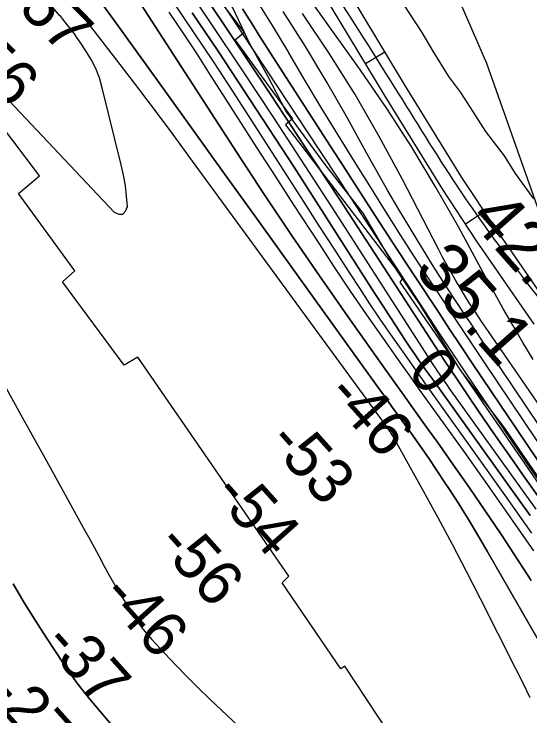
# Model space of a CAD drawing. Extents: x 3245246 to 3283090, y 806824 to 832173.
# Drawn here: x 3270426 to 3271110, y 818378 to 819309 of the extents above; entities that cross this region are included whole.
import ezdxf

# ---------------------------------------------------------------- set-up
doc = ezdxf.new("R2010")
doc.units = 0
for name, color, linetype in [('V-RIVR-EDGE', 7, 'Continuous'), ('V-RIVR-RANG', 7, 'Continuous'), ('V-ROAD-CNTR', 7, 'Continuous'), ('V-RRAP-RVMT', 7, 'Continuous'), ('V-SITE-VEGE', 7, 'Continuous'), ('V-TOPO-DPTH', 7, 'Continuous'), ('V-TOPO-MAJR', 7, 'Continuous'), ('V-TOPO-MINR', 7, 'Continuous'), ('V-TOPO-WATR', 7, 'Continuous'), ('V-WETL-SWMP', 7, 'Continuous')]:
    doc.layers.add(name, color=color, linetype=linetype)

msp = doc.modelspace()

# ---------------------------------------------------------------- linework, layer by layer
at = {"layer": 'V-RIVR-EDGE'}
msp.add_lwpolyline([(3271126.46, 818687.14), (3271077.08, 818759.41), (3271017.29, 818837.8), (3270964.91, 818923.13), (3270933.72, 818969.28), (3270889.14, 819044.59), (3270838.88, 819109.05), (3270786.89, 819180.47), (3270762.66, 819226.17), (3270738.43, 819270.13), (3270716.38, 819317.13), (3270684.76, 819361.98), (3270641.86, 819418.6), (3270597.25, 819482.17), (3270572.13, 819521.35), (3270540.92, 819554.9), (3270518.83, 819587.99)], dxfattribs=at)
at = {"layer": 'V-ROAD-CNTR'}
for p, q in [((3270917.85, 819258.03), (3270892.16, 819242.53)), ((3271049.85, 819046.46), (3271024.81, 819029.94))]:
    msp.add_line(p, q, dxfattribs=at)
for points in [[(3269843.4, 820720.01), (3269850.17, 820706.17), (3269882.17, 820651.66), (3269977.9, 820546.49), (3270017.59, 820500.24), (3270105.1, 820401.13), (3270161.44, 820338.84), (3270271.07, 820208.57), (3270367.8, 820073.22), (3270400.77, 820019.63), (3270480.26, 819915.46), (3270531.02, 819842.71), (3270596.3, 819744.33), (3270689.08, 819609.75), (3270760.57, 819510.58), (3270844.44, 819379.61), (3270883.47, 819315.02), (3270943.57, 819215.39), (3271019.73, 819092.11), (3271064.12, 819024.84), (3271139.99, 818915.3)], [(3269823.72, 820691.96), (3269857.88, 820633.78), (3269955.42, 820526.62), (3269994.96, 820480.54), (3270082.73, 820381.14), (3270138.83, 820319.11), (3270247.35, 820190.16), (3270342.79, 820056.62), (3270376.01, 820002.63), (3270456.03, 819897.77), (3270506.22, 819825.84), (3270571.45, 819727.53), (3270664.56, 819592.46), (3270735.75, 819493.7), (3270818.96, 819363.76), (3270857.79, 819299.51), (3270917.97, 819199.76), (3270994.44, 819075.96), (3271039.26, 819008.03), (3271115.77, 818897.58)]]:
    msp.add_lwpolyline(points, dxfattribs=at)
for points in [[(3268554.95, 824466.19), (3268928.09, 824288.38), (3269383.1, 824061.94), (3269668.74, 823890.07), (3270076.6, 823640.14), (3270419.33, 823451), (3270842.02, 823197.94), (3271162.23, 823029.36), (3271548.34, 822792.54), (3271898.38, 822578.38), (3272236.86, 822400.28), (3272509.78, 822239.3), (3272743.9, 822091.31), (3273013.63, 821941.14), (3273341.05, 821721.19), (3273731.8, 821490.06), (3274189.22, 821174.99), (3274593.6, 820901.16), (3274916.65, 820684.25), (3275373.15, 820360.04), (3275676.64, 820160.98), (3275802.37, 820045.11), (3275896.21, 819927.97), (3275965.24, 819818.62), (3276015.07, 819699.55), (3276044.42, 819586.74), (3276100.52, 819412.97), (3276190.86, 819208.33), (3276292.53, 819051.84), (3276415.54, 818926.3), (3276568.23, 818833.94), (3276716.18, 818768.83), (3276924.78, 818729.04), (3277119.88, 818725), (3277260.84, 818758.15)], [(3265843.13, 823432.94), (3265858.98, 823417.12), (3265884.36, 823393.48), (3265921.56, 823385.9), (3265988.57, 823351.07), (3266047.21, 823332.33), (3266110.89, 823317.69), (3266174.63, 823302.49), (3266237.94, 823256.14), (3266318.96, 823213.69), (3266446.25, 823144.04), (3266598.22, 823070.18), (3266698.27, 823024.21), (3266809.76, 822977.55), (3266902.83, 822954.65), (3266981.51, 822929.37), (3267047.02, 822922.93), (3267126.67, 822926.97), (3267196.8, 822934.46), (3267240.76, 822931.16), (3267315.46, 822929.02), (3267389.48, 822902.91), (3267472.52, 822855.33), (3267548.21, 822799.11), (3267673.18, 822703.23), (3267729.53, 822659.19), (3267800.82, 822580.02), (3267841.58, 822514.78), (3267890.36, 822443.64), (3267961.46, 822390.31), (3268026.22, 822347.95), (3268097.47, 822313.66), (3268226.82, 822221.48), (3268328.91, 822136.16), (3268437.97, 822030.19), (3268539.63, 821913.73), (3268611.4, 821855.02), (3268669.68, 821832.99), (3268741.62, 821835.21), (3268780.98, 821862.31), (3268824.18, 821916.6), (3268873.06, 822006.27), (3268932.52, 822098.07), (3268972.12, 822145.49), (3269019.4, 822162.03), (3269055.98, 822158.33), (3269086.75, 822138.72), (3269215.73, 821995.56), (3269467.12, 821682.49), (3269665.02, 821425.34), (3269890.24, 821132.34), (3269935.57, 821060.84), (3269937.76, 820947.01), (3269911.92, 820878.37), (3269882.42, 820803.43), (3269850.37, 820754.68), (3269820.83, 820702.94), (3269847.45, 820661.45), (3269995.31, 820504.9), (3270135.08, 820342.32), (3270215.8, 820249.25), (3270280.88, 820161.54), (3270409.84, 819983.24), (3270585.16, 819734.7), (3270723.07, 819531.19), (3270847.77, 819342.24), (3270941.21, 819194.89), (3271024.16, 819065.03), (3271103.72, 818955.95), (3271217.86, 818809.2), (3271322.11, 818665.04), (3271450.94, 818481.15), (3271547.8, 818329.85), (3271656.16, 818158.96), (3271778.9, 817965.4), (3271939.04, 817707.54), (3272036.56, 817466.51), (3272126.72, 817285.29), (3272211.94, 817051.13), (3272318, 816867.47), (3272429.35, 816683.19), (3272508.65, 816556.22), (3272571.56, 816398.68), (3272670.41, 816197), (3272779.92, 816022.86), (3272872.13, 815803.22), (3272964.65, 815556.57)]]:
    msp.add_spline(points, degree=3, dxfattribs=at)
at = {"layer": 'V-RRAP-RVMT'}
for p, q in [((3270576.47, 819485.37), (3270731.47, 819284.38)), ((3270576.47, 819485.37), (3270731.47, 819284.38)), ((3270459.93, 819093.98), (3270248.21, 819374.66)), ((3270459.93, 819093.98), (3270248.21, 819374.66)), ((3270731.47, 819284.38), (3270719.54, 819273.97)), ((3270731.47, 819284.38), (3270719.54, 819273.97)), ((3270719.54, 819273.97), (3270795.32, 819169.81)), ((3270719.54, 819273.97), (3270795.32, 819169.81)), ((3270795.32, 819169.81), (3270786.18, 819161.78)), ((3270795.32, 819169.81), (3270786.18, 819161.78)), ((3270786.18, 819161.78), (3270942.07, 818958.53)), ((3270786.18, 819161.78), (3270942.07, 818958.53)), ((3270432.17, 819070.79), (3270459.93, 819093.98)), ((3270432.17, 819070.79), (3270459.93, 819093.98)), ((3270506.73, 818968.19), (3270432.17, 819070.79)), ((3270506.73, 818968.19), (3270432.17, 819070.79)), ((3270490.26, 818953.79), (3270506.73, 818968.19)), ((3270490.26, 818953.79), (3270506.73, 818968.19)), ((3270572.42, 818843.06), (3270490.26, 818953.79)), ((3270572.42, 818843.06), (3270490.26, 818953.79)), ((3270942.07, 818958.53), (3270937.79, 818952.98)), ((3270942.07, 818958.53), (3270937.79, 818952.98)), ((3270937.79, 818952.98), (3271222.9, 818538.45)), ((3270937.79, 818952.98), (3271222.9, 818538.45)), ((3270590.46, 818853.51), (3270572.42, 818843.06)), ((3270590.46, 818853.51), (3270572.42, 818843.06)), ((3270790.66, 818563.47), (3270590.46, 818853.51)), ((3270790.66, 818563.47), (3270590.46, 818853.51)), ((3270781.69, 818554.58), (3270790.66, 818563.47)), ((3270781.69, 818554.58), (3270790.66, 818563.47)), ((3270859.83, 818440.41), (3270781.69, 818554.58)), ((3270859.83, 818440.41), (3270781.69, 818554.58)), ((3270864.98, 818443.82), (3270859.83, 818440.41)), ((3270864.98, 818443.82), (3270859.83, 818440.41)), ((3270934.23, 818339.06), (3270864.98, 818443.82)), ((3270934.23, 818339.06), (3270864.98, 818443.82))]:
    msp.add_line(p, q, dxfattribs=at)
at = {"layer": 'V-SITE-VEGE'}
for p, q in [((3270967.57, 819284.18), (3270943.09, 819321.33)), ((3270982.24, 819259.42), (3270967.57, 819284.18)), ((3271003.04, 819225.99), (3270982.24, 819259.42)), ((3271018.97, 819204.92), (3271003.04, 819225.99)), ((3271038.55, 819173.96), (3271018.97, 819204.92)), ((3271052.01, 819152.92), (3271038.55, 819173.96)), ((3271076.52, 819120.7), (3271052.01, 819152.92)), ((3271091.2, 819097.17), (3271076.52, 819120.7)), ((3271115.7, 819063.72), (3271091.2, 819097.17))]:
    msp.add_line(p, q, dxfattribs=at)
at = {"layer": 'V-TOPO-DPTH'}
for points in [[(3270633.36, 819401.85), (3270719.25, 819273.05), (3270765.92, 819202.77), (3270812.4, 819132.38), (3270858.61, 819061.8), (3270904.64, 818991.1), (3270962.02, 818902.59), (3270979.31, 818876.12), (3270996.72, 818849.73), (3271014.31, 818823.45), (3271032.02, 818797.26), (3271049.89, 818771.17), (3271067.86, 818745.16), (3271085.98, 818719.25), (3271104.2, 818693.41), (3271158.62, 818616.7)], [(3271158.62, 818616.7), (3271104.2, 818693.41), (3271085.98, 818719.25), (3271067.86, 818745.16), (3271049.89, 818771.17), (3271032.02, 818797.26), (3271014.31, 818823.45), (3270996.72, 818849.73), (3270979.31, 818876.12), (3270962.02, 818902.59), (3270904.64, 818991.1), (3270858.61, 819061.8), (3270812.4, 819132.38), (3270765.92, 819202.77), (3270719.25, 819273.05), (3270633.36, 819401.85)], [(3271175.17, 818385.21), (3271053.66, 818596.5), (3271041.34, 818617.51), (3271028.8, 818638.38), (3271015.91, 818659.04), (3271002.79, 818679.56), (3270998.17, 818686.65), (3270987.07, 818703.44), (3270975.82, 818720.12), (3270964.33, 818736.64), (3270952.69, 818753.06), (3270940.93, 818769.4), (3270929.18, 818785.73), (3270917.43, 818802.07), (3270905.68, 818818.41), (3270796.17, 818970.71), (3270751.27, 819033.16), (3270706.37, 819095.6), (3270661.47, 819158.04), (3270616.57, 819220.49), (3270561.73, 819296.76), (3270544.19, 819321.02)], [(3270544.19, 819321.02), (3270561.73, 819296.76), (3270616.57, 819220.49), (3270661.47, 819158.04), (3270706.37, 819095.6), (3270751.27, 819033.16), (3270796.17, 818970.71), (3270905.68, 818818.41), (3270917.43, 818802.07), (3270929.18, 818785.73), (3270940.93, 818769.4), (3270952.69, 818753.06), (3270964.33, 818736.64), (3270975.82, 818720.12), (3270987.07, 818703.44), (3270998.17, 818686.65), (3271002.79, 818679.56), (3271015.91, 818659.04), (3271028.8, 818638.38), (3271041.34, 818617.51), (3271053.66, 818596.5), (3271175.17, 818385.21)], [(3270594.48, 819322.02), (3270721.59, 819125.12), (3270757.55, 819070.22), (3270793.98, 819015.64), (3270831.13, 818961.54), (3270868.75, 818907.77), (3270914.18, 818843.75), (3270929.47, 818822.24), (3270944.78, 818800.76), (3270960.13, 818779.29), (3270975.5, 818757.85), (3270987.78, 818740.76), (3271009.14, 818710.67), (3271030.27, 818680.42), (3271051.07, 818649.94), (3271071.65, 818619.31), (3271089.96, 818591.7), (3271112.23, 818557.58)], [(3270594.48, 819322.02), (3270721.59, 819125.12), (3270757.55, 819070.22), (3270793.98, 819015.64), (3270831.13, 818961.54), (3270868.75, 818907.77), (3270914.18, 818843.75), (3270929.47, 818822.24), (3270944.78, 818800.76), (3270960.13, 818779.29), (3270975.5, 818757.85), (3270987.78, 818740.76), (3271009.14, 818710.67), (3271030.27, 818680.42), (3271051.07, 818649.94), (3271071.65, 818619.31), (3271089.96, 818591.7), (3271112.23, 818557.58)], [(3270729.14, 819315.53), (3270741.4, 819296.22), (3270753.71, 819276.95), (3270836.56, 819147.81), (3270866.58, 819101.17), (3270896.71, 819054.59), (3270926.97, 819008.1), (3270957.33, 818961.67), (3270989.4, 818912.8), (3271003.85, 818890.89), (3271018.34, 818869.01), (3271032.93, 818847.19), (3271047.57, 818825.41), (3271165.94, 818650.01)], [(3271115.76, 818596.67), (3271085.11, 818640.79), (3271054.15, 818684.7), (3271023, 818728.48), (3270978.46, 818790.63), (3270969.44, 818803.23), (3270960.44, 818815.85), (3270951.46, 818828.48), (3270942.5, 818841.13), (3270916.16, 818878.35), (3270894.23, 818909.74), (3270872.56, 818941.31), (3270851.27, 818973.13), (3270830.23, 819005.12), (3270797.37, 819055.76), (3270772.82, 819093.69), (3270748.33, 819131.67), (3270723.95, 819169.72), (3270699.63, 819207.81), (3270686.95, 819227.73), (3270668.87, 819255.78), (3270650.57, 819283.69), (3270631.95, 819311.39)], [(3271115.76, 818596.67), (3271085.11, 818640.79), (3271054.15, 818684.7), (3271023, 818728.48), (3270978.46, 818790.63), (3270969.44, 818803.23), (3270960.44, 818815.85), (3270951.46, 818828.48), (3270942.5, 818841.13), (3270916.16, 818878.35), (3270894.23, 818909.74), (3270872.56, 818941.31), (3270851.27, 818973.13), (3270830.23, 819005.12), (3270797.37, 819055.76), (3270772.82, 819093.69), (3270748.33, 819131.67), (3270723.95, 819169.72), (3270699.63, 819207.81), (3270686.95, 819227.73), (3270668.87, 819255.78), (3270650.57, 819283.69), (3270631.95, 819311.39)], [(3270662.56, 819310.28), (3270696.79, 819259.44), (3270730.74, 819208.42), (3270764.27, 819157.12), (3270797.53, 819105.65), (3270896.72, 818950.73), (3270905.71, 818936.73), (3270914.73, 818922.73), (3270923.79, 818908.76), (3270932.87, 818894.81), (3270939.1, 818885.26), (3270945.13, 818876.12), (3270951.22, 818867.03), (3270957.41, 818858.01), (3270963.67, 818849.03), (3270971.14, 818838.43), (3270973.72, 818834.79), (3270976.3, 818831.14), (3270978.9, 818827.51), (3270981.5, 818823.87), (3271079.5, 818687.39), (3271110.65, 818643.68)], [(3271110.65, 818643.68), (3271079.5, 818687.39), (3270981.5, 818823.87), (3270978.9, 818827.51), (3270976.3, 818831.14), (3270973.72, 818834.79), (3270971.14, 818838.43), (3270963.67, 818849.03), (3270957.41, 818858.01), (3270951.22, 818867.03), (3270945.13, 818876.12), (3270939.1, 818885.26), (3270932.87, 818894.81), (3270923.79, 818908.76), (3270914.73, 818922.73), (3270905.71, 818936.73), (3270896.72, 818950.73), (3270797.53, 819105.65), (3270764.27, 819157.12), (3270730.74, 819208.42), (3270696.79, 819259.44), (3270662.56, 819310.28)], [(3270425.24, 818553.18), (3270439.33, 818528.91), (3270454.05, 818505.04), (3270469.21, 818481.42), (3270492.26, 818446.51), (3270500.91, 818433.92), (3270509.84, 818421.54), (3270519.21, 818409.49), (3270528.87, 818397.65), (3270569.75, 818349.32)], [(3270569.75, 818349.32), (3270528.87, 818397.65), (3270519.21, 818409.49), (3270509.84, 818421.54), (3270500.91, 818433.92), (3270492.26, 818446.51), (3270469.21, 818481.42), (3270454.05, 818505.04), (3270439.33, 818528.91), (3270425.24, 818553.18)]]:
    msp.add_lwpolyline(points, dxfattribs=at)
at = {"layer": 'V-TOPO-MAJR'}
for points in [[(3271110.77, 818401.83), (3271101.4, 818421.16), (3271091.84, 818440.4), (3271044.78, 818533.39), (3271026.36, 818569.3), (3271007.67, 818605.07), (3270988.59, 818640.63), (3270969.24, 818676.05), (3270933.96, 818739.77), (3270932.02, 818743.2), (3270930.02, 818746.61), (3270927.96, 818749.98), (3270925.86, 818753.32), (3270925.21, 818754.33), (3270923.37, 818757.13), (3270921.5, 818759.92), (3270919.59, 818762.67), (3270917.65, 818765.41), (3270916.23, 818767.38), (3270914.98, 818769.11), (3270913.72, 818770.84), (3270912.47, 818772.57), (3270911.21, 818774.3), (3270663.05, 819113.75), (3270637.13, 819148.9), (3270611.02, 819183.91), (3270584.64, 819218.71), (3270558.06, 819253.37), (3270521.78, 819300.31), (3270513.16, 819311.36)], [(3271124.93, 818787.09), (3271099.64, 818823.53), (3271055.46, 818887.61), (3271052.38, 818892.1), (3271049.32, 818896.61), (3271046.28, 818901.13), (3271043.27, 818905.66), (3271036.4, 818916.05), (3271030.04, 818925.84), (3271023.79, 818935.7), (3271017.71, 818945.66), (3271011.73, 818955.68), (3271011.69, 818955.74), (3271005.86, 818965.89), (3271000.14, 818976.11), (3270994.58, 818986.41), (3270989.14, 818996.78), (3270941.11, 819090.08), (3270910.63, 819146.47), (3270878.66, 819201.96), (3270844.47, 819256.12), (3270808.79, 819309.38)], [(3270405.67, 818830.22), (3270437.47, 818773.19), (3270469.18, 818716.11), (3270518.53, 818627.07), (3270525.47, 818614.46), (3270532.36, 818601.82), (3270539.17, 818589.14), (3270545.94, 818576.44), (3270552.82, 818563.8), (3270559.9, 818551.27), (3270567.27, 818538.92), (3270574.84, 818526.69), (3270587.26, 818507.14), (3270592.23, 818499.77), (3270597.46, 818492.6), (3270603.07, 818485.73), (3270608.93, 818479.05), (3270625.99, 818460.66), (3270640.73, 818445.09), (3270655.68, 818429.72), (3270670.92, 818414.65), (3270686.37, 818399.79), (3270797.17, 818295.29)]]:
    msp.add_lwpolyline(points, dxfattribs=at)
at = {"layer": 'V-TOPO-MINR'}
for points in [[(3271114.57, 818850.43), (3271100.88, 818873.05), (3271087.61, 818895.93), (3271074.49, 818918.9), (3271061.6, 818942), (3271048.86, 818965.18), (3271015.57, 819026.48), (3270985.34, 819079.78), (3270953.84, 819132.29), (3270920.43, 819183.6), (3270885.74, 819234.11), (3270700.27, 819493.85), (3270695.78, 819500.11), (3270691.27, 819506.35), (3270686.72, 819512.58), (3270682.16, 819518.79), (3270677.67, 819525.05), (3270673.3, 819531.38), (3270669.11, 819537.84), (3270665.04, 819544.38), (3270664.9, 819544.6), (3270661.77, 819551.46), (3270659.73, 819558.5), (3270234.1, 820399.59)], [(3270412.74, 819201.36), (3270558.9, 819045.85), (3270565.19, 819043.41), (3270570.42, 819043.44), (3270574.06, 819047.2), (3270576.64, 819053.44), (3270575.5, 819067.41), (3270573.83, 819081.31), (3270571.39, 819095.09), (3270568.43, 819108.79), (3270543.28, 819211.11), (3270539.37, 819223.99), (3270534.6, 819236.49), (3270528.54, 819248.42), (3270521.61, 819259.97), (3270514.63, 819270.3), (3270510.45, 819276.33), (3270506.18, 819282.29), (3270501.77, 819288.14), (3270497.25, 819293.92), (3270490.73, 819302.08), (3270489.4, 819303.72), (3270488.06, 819305.36), (3270486.71, 819306.98), (3270485.34, 819308.59), (3270118.98, 819735.96)], [(3271133.69, 818673.65), (3271110.06, 818708.06), (3271086.55, 818742.57), (3271044.96, 818803.97), (3271026.28, 818831.7), (3271007.69, 818859.5), (3270989.24, 818887.39), (3270970.88, 818915.35), (3270930.86, 818976.64), (3270892.51, 819035.25), (3270854.1, 819093.82), (3270815.6, 819152.33), (3270777.03, 819210.79), (3270627.79, 819436.61)], [(3271118.56, 818652.33), (3271003.89, 818812.33), (3271000.7, 818816.81), (3270997.53, 818821.3), (3270994.39, 818825.81), (3270991.27, 818830.33), (3270988.18, 818834.88), (3270985.12, 818839.45), (3270982.1, 818844.04), (3270979.1, 818848.65), (3270853.22, 819044.43), (3270812.29, 819107.66), (3270771.09, 819170.72), (3270729.51, 819233.52), (3270687.66, 819296.15), (3270640.19, 819366.73)], [(3271113.14, 818620.33), (3271077.21, 818671.29), (3271041.04, 818722.08), (3270979.98, 818807.19), (3270974.15, 818815.32), (3270968.34, 818823.47), (3270962.55, 818831.62), (3270956.77, 818839.79), (3270939.9, 818863.67), (3270925.81, 818883.86), (3270911.88, 818904.16), (3270898.18, 818924.61), (3270884.63, 818945.17), (3270871.14, 818965.91), (3270851, 818996.95), (3270830.91, 819028.02), (3270810.91, 819059.14), (3270790.96, 819090.3), (3270742.19, 819166.69), (3270716.53, 819206.45), (3270690.62, 819246.03), (3270664.31, 819285.36), (3270637.74, 819324.52)], [(3271242.67, 818560.48), (3271050.17, 818846.45), (3271039.48, 818862.39), (3271028.82, 818878.35), (3271018.2, 818894.34), (3271007.62, 818910.35), (3270983.78, 818946.55), (3270961.43, 818980.76), (3270939.28, 819015.1), (3270917.4, 819049.61), (3270895.7, 819084.24), (3270877.77, 819113.11), (3270855.67, 819149), (3270833.74, 819185.01), (3270812.07, 819221.17), (3270790.59, 819257.44), (3270790.51, 819257.57), (3270768.86, 819293.65), (3270746.76, 819329.44)], [(3271175.17, 818385.21), (3271053.66, 818596.5), (3271041.34, 818617.51), (3271028.8, 818638.38), (3271015.91, 818659.04), (3271002.79, 818679.56), (3270998.17, 818686.65), (3270987.07, 818703.44), (3270975.82, 818720.12), (3270964.33, 818736.64), (3270952.69, 818753.06), (3270940.93, 818769.4), (3270929.18, 818785.73), (3270917.43, 818802.07), (3270905.68, 818818.41), (3270796.17, 818970.71), (3270751.27, 819033.16), (3270706.37, 819095.6), (3270661.47, 819158.04), (3270616.57, 819220.49), (3270561.73, 819296.76), (3270544.19, 819321.02)], [(3271112.23, 818557.58), (3271089.96, 818591.7), (3271071.65, 818619.31), (3271051.07, 818649.94), (3271030.27, 818680.42), (3271009.14, 818710.67), (3270987.78, 818740.76), (3270975.5, 818757.85), (3270960.13, 818779.29), (3270944.78, 818800.76), (3270929.47, 818822.24), (3270914.18, 818843.75), (3270868.75, 818907.77), (3270831.13, 818961.54), (3270793.98, 819015.64), (3270757.55, 819070.22), (3270721.59, 819125.12), (3270594.48, 819322.02)], [(3271165.94, 818650.01), (3271047.57, 818825.41), (3271032.93, 818847.19), (3271018.34, 818869.01), (3271003.85, 818890.89), (3270989.4, 818912.8), (3270957.33, 818961.67), (3270926.97, 819008.1), (3270896.71, 819054.59), (3270866.58, 819101.17), (3270836.56, 819147.81), (3270753.71, 819276.95), (3270741.4, 819296.22), (3270729.14, 819315.53)], [(3271115.76, 818596.67), (3271085.11, 818640.79), (3271054.15, 818684.7), (3271023, 818728.48), (3270978.46, 818790.63), (3270969.44, 818803.23), (3270960.44, 818815.85), (3270951.46, 818828.48), (3270942.5, 818841.13), (3270916.16, 818878.35), (3270894.23, 818909.74), (3270872.56, 818941.31), (3270851.27, 818973.13), (3270830.23, 819005.12), (3270797.37, 819055.76), (3270772.82, 819093.69), (3270748.33, 819131.67), (3270723.95, 819169.72), (3270699.63, 819207.81), (3270686.95, 819227.73), (3270668.87, 819255.78), (3270650.57, 819283.69), (3270631.95, 819311.39)], [(3271110.65, 818643.68), (3271079.5, 818687.39), (3270981.5, 818823.87), (3270978.9, 818827.51), (3270976.3, 818831.14), (3270973.72, 818834.79), (3270971.14, 818838.43), (3270963.67, 818849.03), (3270957.41, 818858.01), (3270951.22, 818867.03), (3270945.13, 818876.12), (3270939.1, 818885.26), (3270932.87, 818894.81), (3270923.79, 818908.76), (3270914.73, 818922.73), (3270905.71, 818936.73), (3270896.72, 818950.73), (3270797.53, 819105.65), (3270764.27, 819157.12), (3270730.74, 819208.42), (3270696.79, 819259.44), (3270662.56, 819310.28)], [(3271317.5, 818473.13), (3271052.77, 818867.17), (3271045.95, 818877.35), (3271039.14, 818887.55), (3271032.35, 818897.75), (3271025.58, 818907.97), (3271010.13, 818931.34), (3270995.79, 818953.34), (3270981.64, 818975.46), (3270967.76, 818997.75), (3270954.07, 819020.16), (3270951.4, 819024.59), (3270936.66, 819049.38), (3270922.11, 819074.29), (3270907.84, 819099.36), (3270893.77, 819124.54), (3270868.38, 819170.59), (3270841.05, 819218.45), (3270812.79, 819265.72), (3270783.13, 819312.13)], [(3270425.24, 818553.18), (3270439.33, 818528.91), (3270454.05, 818505.04), (3270469.21, 818481.42), (3270492.26, 818446.51), (3270500.91, 818433.92), (3270509.84, 818421.54), (3270519.21, 818409.49), (3270528.87, 818397.65), (3270569.75, 818349.32)]]:
    msp.add_lwpolyline(points, dxfattribs=at)
at = {"layer": 'V-TOPO-WATR'}
msp.add_lwpolyline([(3271158.62, 818616.7), (3271104.2, 818693.41), (3271085.98, 818719.25), (3271067.86, 818745.16), (3271049.89, 818771.17), (3271032.02, 818797.26), (3271014.31, 818823.45), (3270996.72, 818849.73), (3270979.31, 818876.12), (3270962.02, 818902.59), (3270904.64, 818991.1), (3270858.61, 819061.8), (3270812.4, 819132.38), (3270765.92, 819202.77), (3270719.25, 819273.05), (3270633.36, 819401.85)], dxfattribs=at)
at = {"layer": 'V-WETL-SWMP'}
msp.add_lwpolyline([(3271156.4, 818951.88), (3271053.1, 819243.25), (3270865.28, 819675.61), (3270743.2, 820023.37), (3270639.9, 820305.34), (3270527.2, 820521.52), (3270452.08, 820700.1), (3270499.03, 820869.29), (3270592.94, 821019.67), (3270724.41, 821245.25), (3270808.93, 821264.05), (3270940.41, 821226.45), (3271193.96, 821076.07)], dxfattribs=at)

# ---------------------------------------------------------------- texts
at = {"layer": 'V-RIVR-RANG'}
for s, height, rotation, p in [('-57', 60, 314.42978, (3270411.82, 819334.3)), ('-56', 60, 314.42978, (3270340.24, 819264.47)), ('42.4', 67, 311.53833, (3271028.31, 819036.95)), ('35.1', 67, 311.53833, (3270955.2, 818968.68)), ('0', 60, 311.81014, (3270946.19, 818833.18)), ('-46', 60, 311.81014, (3270838.9, 818803.13)), ('-53', 60, 311.81014, (3270761.06, 818740.16)), ('-54', 60, 311.81014, (3270688.42, 818671.37)), ('-56', 60, 311.81014, (3270613.57, 818605.06)), ('-46', 60, 311.81014, (3270540.14, 818537.15)), ('-37', 60, 311.81014, (3270463.25, 818473.12)), ('-27', 60, 311.81014, (3270388.87, 818406.28))]:
    msp.add_text(s, height=height, rotation=rotation, dxfattribs=at).set_placement(p)

doc.saveas('drawing.dxf')
